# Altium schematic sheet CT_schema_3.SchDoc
size 298 x 247 mm
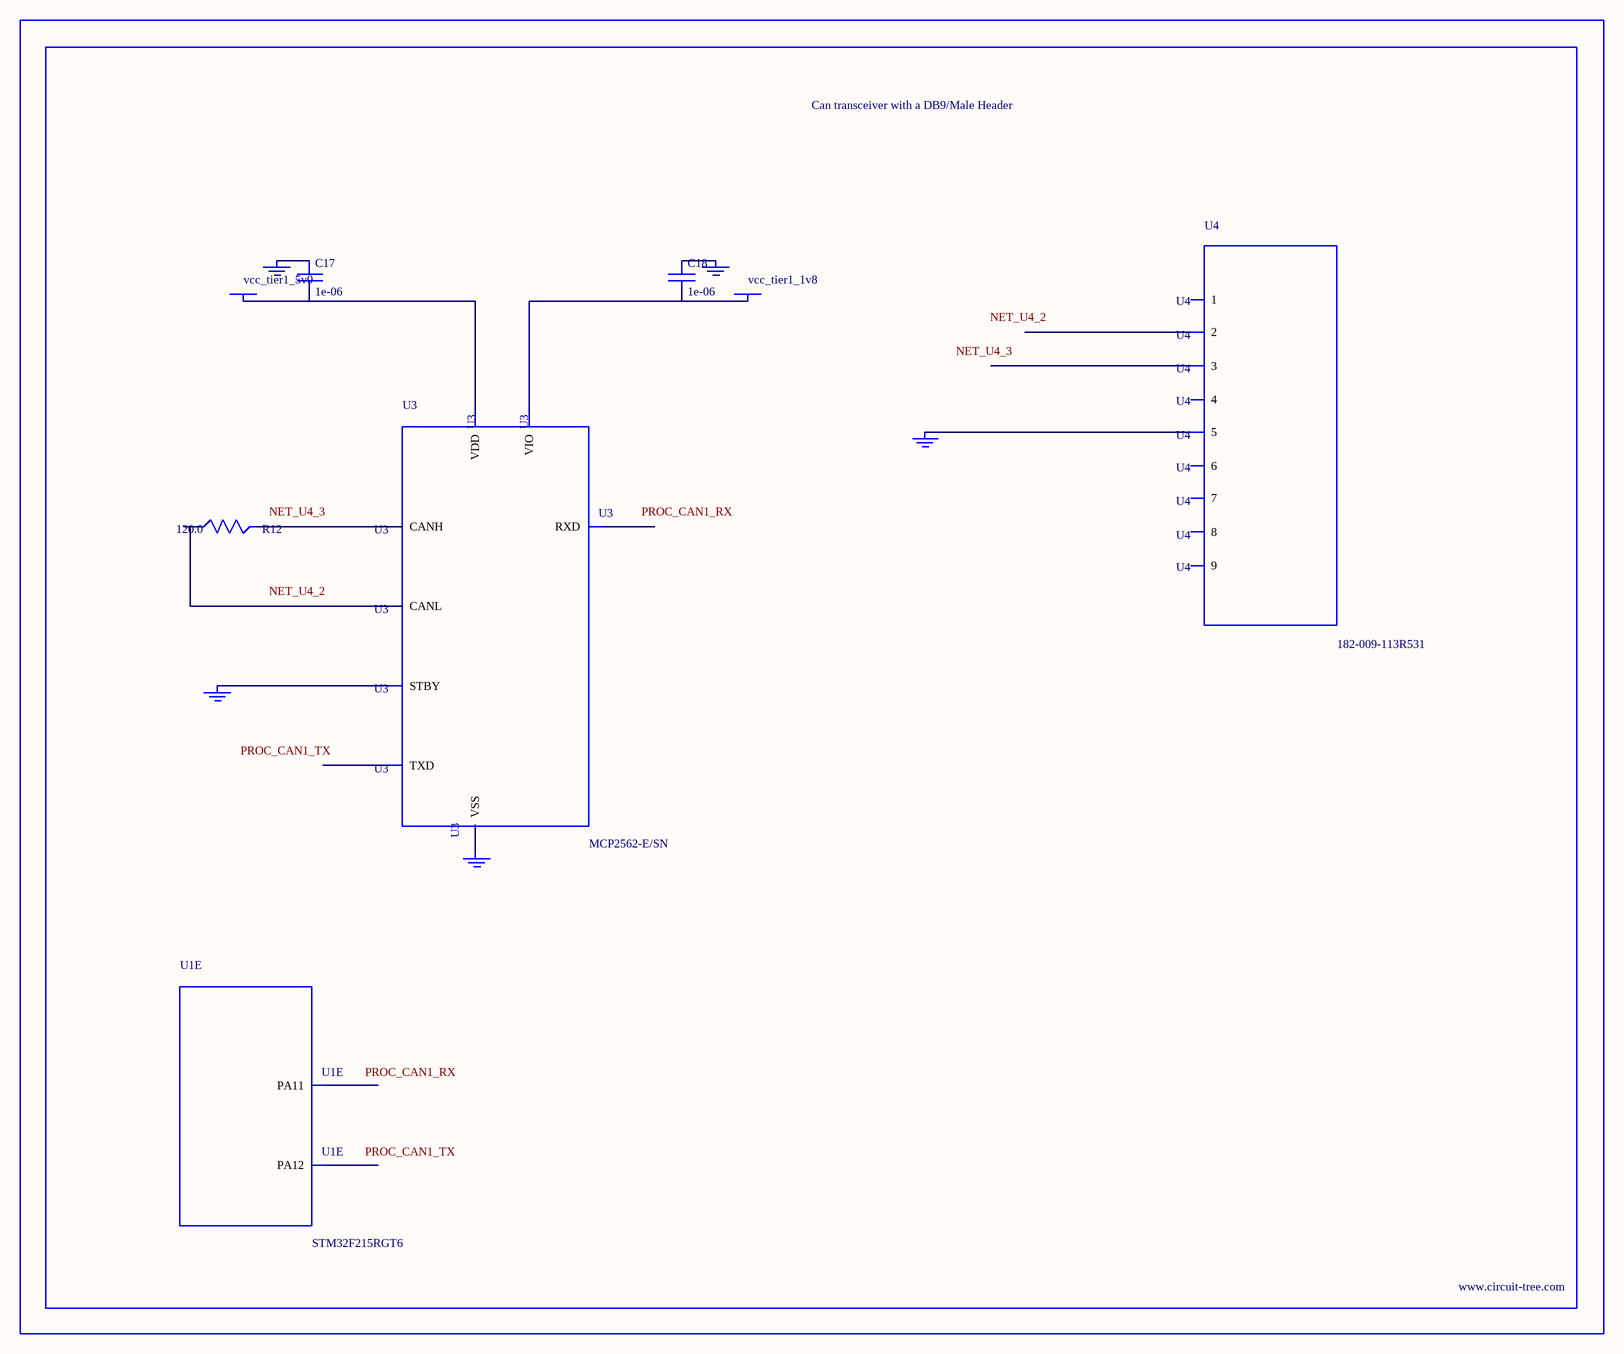
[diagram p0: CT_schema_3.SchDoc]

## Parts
BORDER2  (no value)
C17  1e-06  [C0603]
C18  1e-06  [C0603]
GND_INSTANCE_2_0  (no value)
GND_INSTANCE_2_1  (no value)
GND_INSTANCE_2_2  (no value)
GND_INSTANCE_2_3  (no value)
GND_INSTANCE_2_4  (no value)
POWER_INSTANCE_2_0  vcc_tier1_5v0
POWER_INSTANCE_2_1  vcc_tier1_1v8
R12  120.0  [R0603]
U1  STM32F215RGT6  [LQFP64]  (part E of 7)
U3  MCP2562-E/SN  [SOIC-8]
U4  182-009-113R531  [182-009-MALE]

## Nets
NetC17_1: C17.1 GND_INSTANCE_2_0.0(GND)
NetC17_2: C17.2 POWER_INSTANCE_2_0.0(PWR) U3.3(VDD)
NetC18_1: C18.1 GND_INSTANCE_2_1.0(GND)
NetC18_2: C18.2 POWER_INSTANCE_2_1.0(PWR) U3.5(VIO)
NetGND_INSTANCE_2_2_0: GND_INSTANCE_2_2.0(GND) U3.8(STBY)
NetGND_INSTANCE_2_3_0: GND_INSTANCE_2_3.0(GND) U3.2(VSS)
NetGND_INSTANCE_2_4_0: GND_INSTANCE_2_4.0(GND) U4.5
NetR12_1: R12.1 U3.6(CANL)
NetR12_2: R12.2 U3.7(CANH)

Not connected (* = marked no-connect by the designer): U1 44(PA11) 45(PA12); U3 1(TXD) 4(RXD); U4 1 2 3 4 6 7 8 9

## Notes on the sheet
- Labels drawn without touching a wire or pin: NET_U4_2, NET_U4_3, PROC_CAN1_RX, PROC_CAN1_TX

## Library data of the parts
BORDER2 = BORDER_PAGE2
C17 C18 = C0603C105K3RACTU
GND_INSTANCE_2_0-GND_INSTANCE_2_4 = GND
POWER_INSTANCE_2_0 POWER_INSTANCE_2_1 = PWR
R12 = RC0603JR-07120RL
